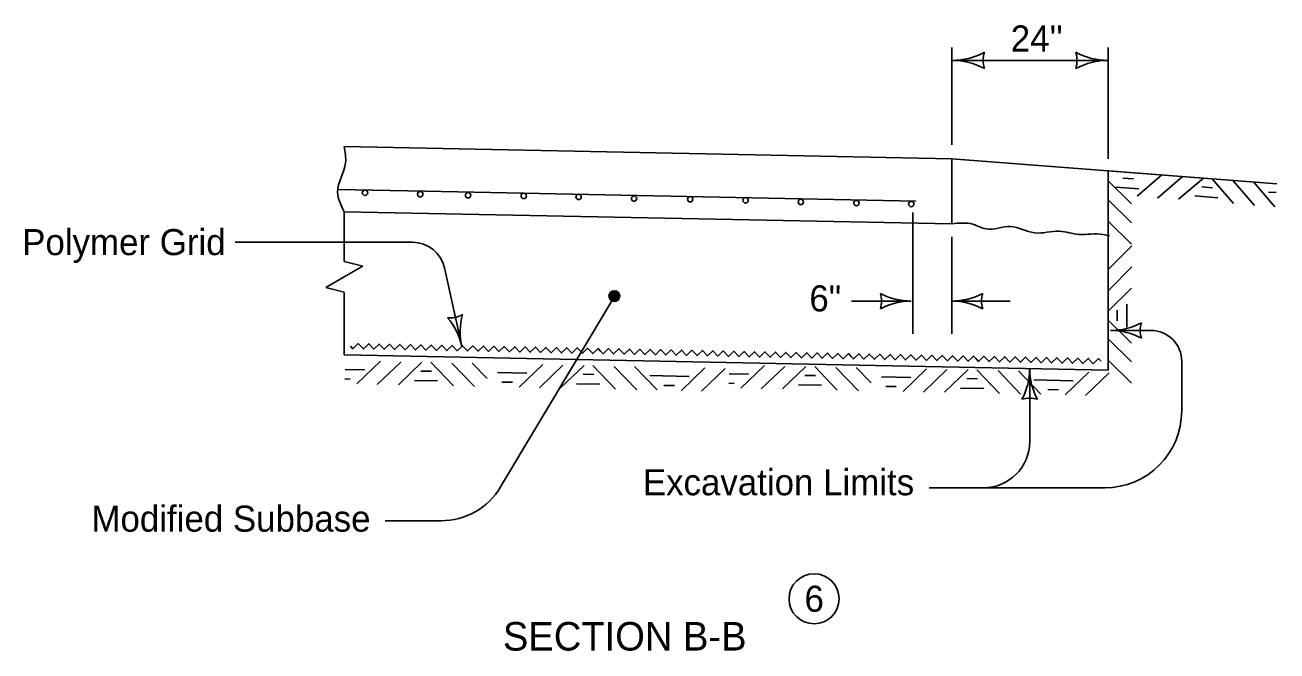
# Model space of a CAD drawing. Extents: x -2134860 to -2124557, y -2139046 to -2137324.
# Drawn here: x -2127592 to -2126824, y -2138207 to -2137823 of the extents above; entities that cross this region are included whole.
import ezdxf

# ---------------------------------------------------------------- set-up
doc = ezdxf.new("R2010")
doc.units = 0
doc.layers.add('BridgeSuperStructureExisting', color=7, linetype='Continuous')
doc.layers.add('dsnStdLabel', color=7, linetype='Continuous')

msp = doc.modelspace()

# ---------------------------------------------------------------- linework, layer by layer
at = {"layer": 'BridgeSuperStructureExisting'}
for p, q in [((-2127023.33, -2137896.81), (-2127023.33, -2137837.11)), ((-2126927.33, -2137905.37), (-2126927.33, -2137837.11)), ((-2127023.33, -2137845.09), (-2126927.33, -2137845.09)), ((-2127023.33, -2137905.37), (-2127396.26, -2137897.89)), ((-2127396.26, -2137897.89), (-2127023.33, -2137905.37)), ((-2127023.33, -2137945.38), (-2127023.33, -2137905.37)), ((-2127023.33, -2137905.37), (-2127023.33, -2137945.38)), ((-2127023.33, -2137905.37), (-2126823.87, -2137920.72)), ((-2126927.33, -2138035.03), (-2126927.33, -2137912.76)), ((-2126927.31, -2137912.78), (-2126823.84, -2137920.75)), ((-2126927.33, -2137918.97), (-2126913.19, -2137933.11)), ((-2126894.4, -2137915.32), (-2126909.58, -2137928.33)), ((-2126882, -2137916.5), (-2126897.19, -2137929.51)), ((-2126869.02, -2137917.27), (-2126884.2, -2137930.28)), ((-2126863.62, -2137917.68), (-2126850.6, -2137932.87)), ((-2126850.67, -2137918.91), (-2126837.65, -2137934.09)), ((-2126838.24, -2137919.64), (-2126825.22, -2137934.82)), ((-2127346.79, -2137925.32), (-2127400.23, -2137924.25)), ((-2127045.43, -2137931.37), (-2127346.79, -2137925.32)), ((-2127286.2, -2137926.54), (-2127286.2, -2137926.54)), ((-2127252.17, -2137927.22), (-2127252.17, -2137927.22)), ((-2127184.11, -2137928.59), (-2127184.11, -2137928.59)), ((-2127150.07, -2137929.27), (-2127150.07, -2137929.27)), ((-2126927.33, -2137930.55), (-2126913.19, -2137944.69)), ((-2127396.26, -2137937.89), (-2127023.33, -2137945.38)), ((-2127396.26, -2137937.89), (-2127023.33, -2137945.38)), ((-2127396.26, -2137938.15), (-2127396.26, -2137968.42)), ((-2127047.33, -2138012.92), (-2127047.33, -2137938.45)), ((-2126927.33, -2137943.61), (-2126913.19, -2137957.75)), ((-2127463.07, -2137956.62), (-2127354.28, -2137956.62)), ((-2127023.33, -2138012.92), (-2127023.33, -2137953.22)), ((-2126927.11, -2137973.04), (-2126912.96, -2137958.9)), ((-2127396.26, -2137968.42), (-2127384.92, -2137971.25)), ((-2127384.92, -2137971.25), (-2127396.26, -2137977.86)), ((-2127334.75, -2137972.32), (-2127324.14, -2138020.45)), ((-2126927.11, -2137985.94), (-2126912.96, -2137971.8)), ((-2127396.26, -2137977.86), (-2127407.61, -2137984.48)), ((-2127407.61, -2137984.48), (-2127396.26, -2137987.32)), ((-2127396.26, -2137987.32), (-2127396.26, -2138025.64)), ((-2127300.28, -2138106.76), (-2127230.47, -2137989.99)), ((-2126927.33, -2137998.95), (-2126913.19, -2137984.81)), ((-2127048.32, -2137992.74), (-2127084.86, -2137992.74)), ((-2126987.55, -2137992.74), (-2127023.33, -2137992.74)), ((-2127328.53, -2138000.53), (-2127327.4, -2138005.63)), ((-2126927.33, -2138004.36), (-2126913.19, -2138018.5)), ((-2126901.2, -2138010.77), (-2126925.92, -2138010.77)), ((-2126927.33, -2138015.93), (-2126913.19, -2138030.08)), ((-2127396.26, -2138025.64), (-2126927.34, -2138035.05)), ((-2126927.33, -2138029), (-2126913.19, -2138043.14)), ((-2127373.99, -2138029.65), (-2127388.41, -2138043.51)), ((-2127361.55, -2138030.13), (-2127375.97, -2138043.98)), ((-2127348.54, -2138030.16), (-2127362.96, -2138044.02)), ((-2127343.13, -2138030.27), (-2127329.27, -2138044.69)), ((-2127330.12, -2138030.76), (-2127316.27, -2138045.18)), ((-2127317.67, -2138030.78), (-2127308.57, -2138040.26)), ((-2127274.46, -2138031.65), (-2127288.88, -2138045.51)), ((-2127262.01, -2138032.13), (-2127276.44, -2138045.98)), ((-2127249, -2138032.16), (-2127263.43, -2138046.02)), ((-2127243.59, -2138032.27), (-2127229.74, -2138046.69)), ((-2127230.59, -2138032.76), (-2127216.74, -2138047.18)), ((-2127218.14, -2138032.78), (-2127204.28, -2138047.2)), ((-2127174.92, -2138033.65), (-2127189.35, -2138047.5)), ((-2127162.48, -2138034.12), (-2127176.9, -2138047.98)), ((-2127138.39, -2138032.29), (-2127152.81, -2138046.14)), ((-2127125.94, -2138032.77), (-2127140.37, -2138046.62)), ((-2127112.93, -2138032.8), (-2127127.36, -2138046.66)), ((-2127107.52, -2138032.91), (-2127093.67, -2138047.33)), ((-2127094.52, -2138033.4), (-2127080.67, -2138047.82)), ((-2127082.07, -2138033.42), (-2127072.97, -2138042.89)), ((-2127038.86, -2138034.29), (-2127053.28, -2138048.14)), ((-2127026.41, -2138034.76), (-2127040.84, -2138048.62)), ((-2127013.4, -2138034.8), (-2127027.83, -2138048.65)), ((-2127007.99, -2138034.91), (-2126994.14, -2138049.33)), ((-2126994.99, -2138035.39), (-2126981.14, -2138049.82)), ((-2126982.54, -2138035.42), (-2126968.68, -2138049.84)), ((-2126975.6, -2138034.08), (-2126975.6, -2138078.94)), ((-2126939.32, -2138036.28), (-2126953.75, -2138050.14)), ((-2126926.88, -2138036.76), (-2126941.3, -2138050.62)), ((-2126882.29, -2138029.67), (-2126882.29, -2138060.03)), ((-2126929.56, -2138107.3), (-2127037.33, -2138107.3)), ((-2127371.08, -2138127.47), (-2127336.8, -2138127.47))]:
    msp.add_line(p, q, dxfattribs=at)
for points in [[(-2126918.39, -2137917.33), (-2126911.88, -2137917.83)], [(-2126922.66, -2137922.87), (-2126908.51, -2137923.96)], [(-2126874.26, -2137928.25), (-2126860.11, -2137929.34)], [(-2126870, -2137922.71), (-2126863.48, -2137923.21)], [(-2126829.1, -2137925.83), (-2126824.26, -2137926.2)], [(-2127230.75, -2137992.7), (-2127229.63, -2137992.2), (-2127227.89, -2137991.67), (-2127227.56, -2137989.9), (-2127227.8, -2137988.36), (-2127228.91, -2137986.93), (-2127230.56, -2137987.07), (-2127232.3, -2137987.32), (-2127233.14, -2137988.7), (-2127233.29, -2137990.17), (-2127232.26, -2137992.08), (-2127230.99, -2137992.24), (-2127229.25, -2137991.8), (-2127227.83, -2137990.69), (-2127227.87, -2137989.04), (-2127228.99, -2137987.71), (-2127230.55, -2137987.56), (-2127232.29, -2137987.9), (-2127232.55, -2137988.88), (-2127232.9, -2137990.06), (-2127232.09, -2137991.49), (-2127230.82, -2137991.46), (-2127229.37, -2137991.23), (-2127228.32, -2137990.41), (-2127228.85, -2137988.97), (-2127229.95, -2137988.12), (-2127231.41, -2137988.07), (-2127231.77, -2137988.86), (-2127232.24, -2137989.75), (-2127231.52, -2137990.9), (-2127230.44, -2137991.16), (-2127229.48, -2137990.64), (-2127229.41, -2137989.57), (-2127229.92, -2137988.8), (-2127230.9, -2137988.54), (-2127231.38, -2137988.95), (-2127231.66, -2137989.54), (-2127231.14, -2137990.4), (-2127230.46, -2137990.57), (-2127229.79, -2137990.16), (-2127229.9, -2137989.58), (-2127230.4, -2137989.21), (-2127231.08, -2137989.23), (-2127231.07, -2137989.72), (-2127230.47, -2137989.99)], [(-2126921.83, -2138004.92), (-2126921.83, -2137998.39)], [(-2126915.98, -2138008.75), (-2126915.98, -2137994.56)], [(-2127392.45, -2138020.31), (-2127390.88, -2138021.94), (-2127387.62, -2138018.8), (-2127384.48, -2138022.07), (-2127381.22, -2138018.93), (-2127378.08, -2138022.2), (-2127374.82, -2138019.06), (-2127371.68, -2138022.32), (-2127368.42, -2138019.19), (-2127365.29, -2138022.45), (-2127362.02, -2138019.32), (-2127358.89, -2138022.58), (-2127355.62, -2138019.45), (-2127352.49, -2138022.71), (-2127349.23, -2138019.57), (-2127346.09, -2138022.84), (-2127342.83, -2138019.7), (-2127339.69, -2138022.97), (-2127336.43, -2138019.83), (-2127333.29, -2138023.09), (-2127330.03, -2138019.96), (-2127326.89, -2138023.22), (-2127323.63, -2138020.09), (-2127320.5, -2138023.35), (-2127317.23, -2138020.22), (-2127315.66, -2138021.85)], [(-2127315.66, -2138021.85), (-2127314.1, -2138023.48), (-2127310.83, -2138020.34), (-2127307.7, -2138023.61), (-2127304.43, -2138020.47), (-2127301.3, -2138023.74), (-2127298.04, -2138020.6), (-2127294.9, -2138023.86), (-2127291.64, -2138020.73), (-2127288.5, -2138023.99), (-2127285.24, -2138020.86), (-2127282.1, -2138024.12), (-2127278.84, -2138020.99), (-2127275.7, -2138024.25), (-2127272.44, -2138021.12), (-2127269.31, -2138024.38), (-2127266.04, -2138021.24), (-2127262.91, -2138024.51), (-2127259.64, -2138021.37), (-2127256.51, -2138024.64), (-2127253.24, -2138021.5), (-2127250.11, -2138024.76), (-2127246.85, -2138021.63), (-2127243.71, -2138024.89), (-2127240.45, -2138021.76), (-2127238.88, -2138023.39)], [(-2127238.88, -2138023.39), (-2127237.31, -2138025.02), (-2127234.05, -2138021.89), (-2127230.91, -2138025.15), (-2127227.65, -2138022.01), (-2127224.51, -2138025.28), (-2127221.25, -2138022.14), (-2127218.12, -2138025.41), (-2127214.85, -2138022.27), (-2127211.72, -2138025.53), (-2127208.45, -2138022.4), (-2127205.32, -2138025.66), (-2127202.05, -2138022.53), (-2127198.92, -2138025.79), (-2127195.66, -2138022.66), (-2127192.52, -2138025.92), (-2127189.26, -2138022.78), (-2127186.12, -2138026.05), (-2127182.86, -2138022.91), (-2127179.72, -2138026.18), (-2127176.46, -2138023.04), (-2127173.32, -2138026.31), (-2127170.06, -2138023.17), (-2127166.93, -2138026.43), (-2127163.66, -2138023.3), (-2127162.09, -2138024.93)], [(-2127162.06, -2138025.03), (-2127160.49, -2138026.66), (-2127157.23, -2138023.53), (-2127154.09, -2138026.79), (-2127150.83, -2138023.66), (-2127147.7, -2138026.92), (-2127144.43, -2138023.79), (-2127141.3, -2138027.05), (-2127138.03, -2138023.91), (-2127134.9, -2138027.18), (-2127131.63, -2138024.04), (-2127128.5, -2138027.31), (-2127125.24, -2138024.17), (-2127122.1, -2138027.43), (-2127118.84, -2138024.3), (-2127115.7, -2138027.56), (-2127112.44, -2138024.43), (-2127109.3, -2138027.69), (-2127106.04, -2138024.56), (-2127102.9, -2138027.82), (-2127099.64, -2138024.68), (-2127096.51, -2138027.95), (-2127093.24, -2138024.81), (-2127090.11, -2138028.08), (-2127086.84, -2138024.94), (-2127085.28, -2138026.57)], [(-2127085.28, -2138026.57), (-2127083.71, -2138028.2), (-2127080.44, -2138025.07), (-2127077.31, -2138028.33), (-2127074.05, -2138025.2), (-2127070.91, -2138028.46), (-2127067.65, -2138025.33), (-2127064.51, -2138028.59), (-2127061.25, -2138025.45), (-2127058.11, -2138028.72), (-2127054.85, -2138025.58), (-2127051.72, -2138028.85), (-2127048.45, -2138025.71), (-2127045.32, -2138028.98), (-2127042.05, -2138025.84), (-2127038.92, -2138029.1), (-2127035.65, -2138025.97), (-2127032.52, -2138029.23), (-2127029.26, -2138026.1), (-2127026.12, -2138029.36), (-2127022.86, -2138026.23), (-2127019.72, -2138029.49), (-2127016.46, -2138026.35), (-2127013.32, -2138029.62), (-2127010.06, -2138026.48), (-2127008.49, -2138028.11)], [(-2127008.49, -2138028.11), (-2127006.92, -2138029.75), (-2127003.66, -2138026.61), (-2127000.53, -2138029.87), (-2126997.26, -2138026.74), (-2126994.13, -2138030), (-2126990.86, -2138026.87), (-2126987.73, -2138030.13), (-2126984.47, -2138027), (-2126981.33, -2138030.26), (-2126978.07, -2138027.12), (-2126974.93, -2138030.39), (-2126971.67, -2138027.25), (-2126968.53, -2138030.52), (-2126965.27, -2138027.38), (-2126962.13, -2138030.65), (-2126958.87, -2138027.51), (-2126955.74, -2138030.77), (-2126952.47, -2138027.64), (-2126949.34, -2138030.9), (-2126946.07, -2138027.77), (-2126942.94, -2138031.03), (-2126939.67, -2138027.9), (-2126936.54, -2138031.16), (-2126933.28, -2138028.02), (-2126931.71, -2138029.66)], [(-2127395.71, -2138034.69), (-2127383.68, -2138034.93)], [(-2127349.21, -2138035.65), (-2127342.67, -2138035.78)], [(-2127302.21, -2138036.57), (-2127284.15, -2138036.93)], [(-2127395.82, -2138040.49), (-2127392.56, -2138040.56)], [(-2127353.15, -2138041.43), (-2127338.96, -2138041.71)], [(-2127299.56, -2138042.42), (-2127293.03, -2138042.55)], [(-2127253.62, -2138043.42), (-2127239.43, -2138043.71)], [(-2127249.67, -2138037.65), (-2127243.14, -2138037.78)], [(-2127208.67, -2138038.45), (-2127184.61, -2138038.93)], [(-2127200.02, -2138044.42), (-2127193.49, -2138044.55)], [(-2127160.22, -2138043.13), (-2127156.96, -2138043.19)], [(-2127160.11, -2138037.33), (-2127148.08, -2138037.57)], [(-2127117.55, -2138044.06), (-2127103.36, -2138044.35)], [(-2127113.6, -2138038.29), (-2127107.07, -2138038.42)], [(-2127066.61, -2138039.21), (-2127048.55, -2138039.57)], [(-2127014.07, -2138040.28), (-2127007.54, -2138040.41)], [(-2126973.07, -2138041.08), (-2126949.01, -2138041.57)], [(-2127063.96, -2138045.06), (-2127057.43, -2138045.19)], [(-2127018.02, -2138046.06), (-2127003.83, -2138046.35)], [(-2126964.42, -2138047.06), (-2126957.89, -2138047.19)]]:
    msp.add_lwpolyline(points, dxfattribs=at)
for centre, radius in [((-2127383.49, -2137926.25), 1.65), ((-2127349.62, -2137927.17), 1.65), ((-2127320.21, -2137927.8), 1.65), ((-2127286.05, -2137928.18), 1.65), ((-2127252.4, -2137928.83), 1.65), ((-2127218.36, -2137929.85), 1.65), ((-2127183.95, -2137930.23), 1.65), ((-2127149.92, -2137930.92), 1.65), ((-2127116.02, -2137931.9), 1.65), ((-2127081.91, -2137932.59), 1.65), ((-2127048.26, -2137933.22), 1.65), ((-2127230.49, -2137989.67), 3.31), ((-2127107.92, -2138175.36), 15.36)]:
    msp.add_circle(centre, radius, dxfattribs=at)
for centre, radius, start, end in [((-2127023.33, -2137802.59), 42.5, 270, 298.07249), ((-2127023.33, -2137887.59), 42.5, 61.92751, 90), ((-2126987.7, -2137845.09), 16.42, 162.26665, 197.73335), ((-2126962.97, -2137845.09), 16.42, 342.26665, 17.73335), ((-2126927.33, -2137802.59), 42.5, 241.92751, 270), ((-2126962.97, -2137845.09), 16.42, 342.26665, 17.73335), ((-2126927.33, -2137802.59), 42.5, 241.92751, 270), ((-2126927.33, -2137887.59), 42.5, 90, 118.07249), ((-2126927.33, -2137887.59), 42.5, 90, 118.07249), ((-2127354.28, -2137976.62), 20, 12.43134, 90), ((-2127082.01, -2137992.74), 15.52, 342.26665, 17.73335), ((-2127048.32, -2137952.56), 40.18, 241.92751, 270), ((-2127082.01, -2137992.74), 15.52, 342.26665, 17.73335), ((-2127048.32, -2137952.56), 40.18, 241.92751, 270), ((-2127023.33, -2137952.56), 40.18, 270, 298.07249), ((-2126989.65, -2137992.74), 15.52, 162.26665, 197.73335), ((-2127048.32, -2138032.91), 40.18, 90, 118.07249), ((-2127048.32, -2138032.91), 40.18, 90, 118.07249), ((-2127023.33, -2138032.91), 40.18, 61.92751, 90), ((-2127331.38, -2137987.55), 15.52, 264.68499, 300.15169), ((-2127363.37, -2138029.08), 40.18, 12.41834, 40.49083), ((-2127284.9, -2138011.81), 40.18, 164.34585, 192.41834), ((-2126925.92, -2137970.59), 40.18, 270, 298.07249), ((-2126925.92, -2137970.59), 40.18, 270, 298.07249), ((-2126892.23, -2138010.76), 15.52, 162.26665, 197.73335), ((-2126892.23, -2138010.76), 15.52, 162.26665, 197.73335), ((-2126925.92, -2138050.94), 40.18, 61.92751, 90), ((-2126925.92, -2138050.94), 40.18, 61.92751, 90), ((-2126901.2, -2138029.67), 18.91, 0, 90), ((-2127015.78, -2138034.08), 40.18, 331.92751, 360), ((-2126935.43, -2138034.08), 40.18, 180, 208.07249), ((-2126975.6, -2138067.77), 15.52, 72.26665, 107.73335), ((-2126929.56, -2138060.03), 47.27, 270, 360), ((-2127003.96, -2138078.94), 28.36, 270, 360), ((-2127336.8, -2138084.93), 42.54, 270, 329.12488)]:
    msp.add_arc(centre, radius, start, end, dxfattribs=at)
for points in [[(-2127396.26, -2137897.89), (-2127395.44, -2137907.9), (-2127400.32, -2137925.95), (-2127396.26, -2137937.89)], [(-2127396.26, -2137897.89), (-2127395.44, -2137907.9), (-2127400.32, -2137925.95), (-2127396.26, -2137937.89)], [(-2127023.33, -2137945.38), (-2127010.38, -2137945.59), (-2127002.25, -2137948.46), (-2126987.43, -2137947.02), (-2126972.6, -2137950.85), (-2126957.3, -2137949.89), (-2126945.34, -2137951.81), (-2126930.52, -2137951.81), (-2126926.69, -2137952.76)]]:
    msp.add_spline(points, degree=3, dxfattribs=at)

# ---------------------------------------------------------------- texts
msp.add_text('SECTION B-B', height=17.5, dxfattribs=at).set_placement((-2127298.85, -2138207.12))
at = {"layer": 'dsnStdLabel'}
for s, p in [("24''", (-2126987.2, -2137839.62)), ('Polymer Grid', (-2127593.87, -2137964.55)), ('6"', (-2127110.8, -2137999.06)), ('Excavation Limits', (-2127212.97, -2138111.86)), ('Modified Subbase', (-2127551.38, -2138134.2)), ('6', (-2127113.79, -2138183.34))]:
    msp.add_text(s, height=16, dxfattribs=at).set_placement(p)

doc.saveas('drawing.dxf')
